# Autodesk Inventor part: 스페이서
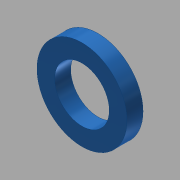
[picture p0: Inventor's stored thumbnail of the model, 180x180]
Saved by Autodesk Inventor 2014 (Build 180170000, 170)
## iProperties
Created: 2018-01
Part Number: 스페이서
Material: 스테인리스강
Document SubType Name: Modeling
Designer: mduedu
Density: 1 g/cm^3
Appearance: 청록색
Author: mduedu
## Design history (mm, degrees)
sketch "스케치1"
  geometry: C1 r 7 at (0, 0); C2 r 4.25 at (0, 0); 1 further point
  constraints: 2 centre point, 2 coincident
  dimensions: "d0" = 14 diameter of C1; "d1" = 8.5 diameter of C2
extrude "돌출1" new body sketch "스케치1" distance "d2" = 2.5; taper "d3" = 0 deg
node "솔리드1"
